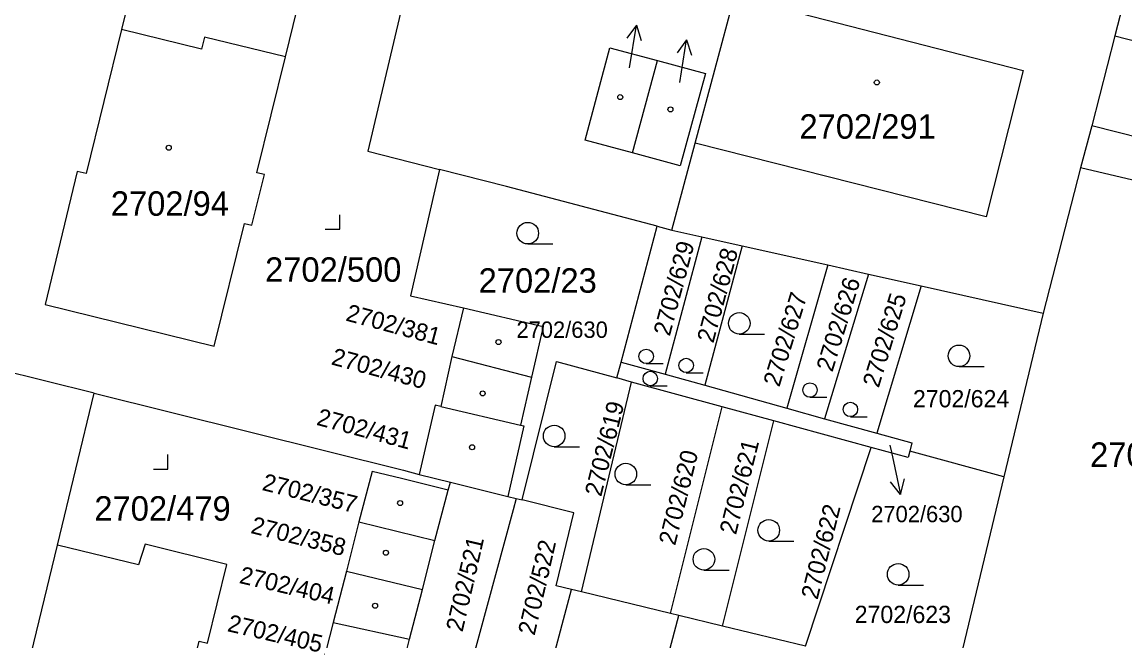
# Model space of a CAD drawing. Extents: x -496682 to -495907, y -1088575 to -1088018.
# Drawn here: x -496634.1 to -496557.4, y -1088480 to -1088436.9 of the extents above; entities that cross this region are included whole.
import ezdxf

# ---------------------------------------------------------------- set-up
doc = ezdxf.new("R2010")
doc.units = 0
for name, color, linetype in [('Hranice parcel', 7, 'Continuous'), ('Parcelní čísla', 7, 'Continuous'), ('Pop  PČ popisy', 7, 'Continuous'), ('Vnitřní kresba', 7, 'Continuous'), ('Značky budov', 7, 'Continuous'), ('Značky kultur', 7, 'Continuous')]:
    doc.layers.add(name, color=color, linetype=linetype)

msp = doc.modelspace()

# ---------------------------------------------------------------- linework, layer by layer
at = {"layer": 'Hranice parcel'}
for p, q in [((-496591.65, -1088446.03), (-496589.92, -1088439.6)), ((-496560.5, -1088447.06), (-496563.11, -1088457.17)), ((-496542.82, -1088451.3), (-496560.5, -1088447.06)), ((-496592.45, -1088460.57), (-496589.94, -1088451.12)), ((-496589.94, -1088451.12), (-496588.92, -1088451.39)), ((-496586.83, -1088451.86), (-496589.39, -1088461.42)), ((-496588.92, -1088451.39), (-496586.83, -1088451.86)), ((-496586.83, -1088451.86), (-496584.04, -1088452.48)), ((-496584.04, -1088452.48), (-496586.63, -1088462.19)), ((-496584.04, -1088452.48), (-496578.08, -1088453.82)), ((-496578.08, -1088453.82), (-496580.92, -1088463.77)), ((-496578.08, -1088453.82), (-496575.25, -1088454.45)), ((-496575.25, -1088454.45), (-496578.3, -1088464.51)), ((-496575.25, -1088454.45), (-496571.59, -1088455.27)), ((-496571.59, -1088455.27), (-496574.67, -1088465.51)), ((-496571.59, -1088455.27), (-496563.11, -1088457.17)), ((-496603.42, -1088456.81), (-496604.23, -1088460.18)), ((-496563.11, -1088457.17), (-496565.84, -1088468.56)), ((-496629.09, -1088462.74), (-496640.95, -1088459.81)), ((-496604.23, -1088460.18), (-496604.99, -1088463.66)), ((-496604.23, -1088460.18), (-496598.69, -1088461.62)), ((-496592.74, -1088461.68), (-496592.45, -1088460.57)), ((-496592.45, -1088460.57), (-496589.39, -1088461.42)), ((-496598.69, -1088461.62), (-496599.45, -1088464.96)), ((-496591.72, -1088461.96), (-496592.74, -1088461.68)), ((-496589.39, -1088461.42), (-496586.63, -1088462.19)), ((-496595.21, -1088476.56), (-496591.72, -1088461.96)), ((-496585.42, -1088463.68), (-496591.72, -1088461.96)), ((-496586.63, -1088462.19), (-496580.92, -1088463.77)), ((-496631.65, -1088473.31), (-496629.09, -1088462.74)), ((-496604.99, -1088463.66), (-496599.45, -1088464.96)), ((-496589.01, -1088478.06), (-496585.42, -1088463.68)), ((-496581.84, -1088464.65), (-496585.42, -1088463.68)), ((-496580.92, -1088463.77), (-496578.3, -1088464.51)), ((-496585.4, -1088478.93), (-496581.84, -1088464.65)), ((-496575.06, -1088466.51), (-496581.84, -1088464.65)), ((-496578.3, -1088464.51), (-496574.67, -1088465.51)), ((-496579.62, -1088480.33), (-496575.06, -1088466.51)), ((-496565.84, -1088468.56), (-496572.37, -1088466.76)), ((-496606.49, -1088468.38), (-496604.32, -1088468.92)), ((-496565.84, -1088468.56), (-496569.26, -1088482.83)), ((-496605.41, -1088472.99), (-496604.48, -1088469.49)), ((-496604.48, -1088469.49), (-496604.32, -1088468.92)), ((-496604.32, -1088468.92), (-496600.33, -1088469.91)), ((-496600.33, -1088469.91), (-496599.74, -1088470.06)), ((-496599.74, -1088470.06), (-496599.34, -1088470.16)), ((-496610.7, -1088471.68), (-496611.55, -1088475.11)), ((-496610.7, -1088471.68), (-496605.41, -1088472.99)), ((-496606.26, -1088476.38), (-496605.41, -1088472.99)), ((-496611.55, -1088475.11), (-496612.47, -1088478.69)), ((-496611.55, -1088475.11), (-496606.26, -1088476.38)), ((-496607.16, -1088479.85), (-496606.26, -1088476.38)), ((-496598.81, -1088487.34), (-496595.91, -1088476.39)), ((-496595.21, -1088476.56), (-496595.91, -1088476.39)), ((-496589.01, -1088478.06), (-496595.21, -1088476.56)), ((-496612.47, -1088478.69), (-496613.22, -1088481.59)), ((-496612.47, -1088478.69), (-496607.16, -1088479.85)), ((-496591.38, -1088489.16), (-496588.43, -1088478.2)), ((-496588.43, -1088478.2), (-496589.01, -1088478.06)), ((-496585.4, -1088478.93), (-496588.43, -1088478.2)), ((-496579.62, -1088480.33), (-496585.4, -1088478.93)), ((-496607.91, -1088482.74), (-496607.16, -1088479.85))]:
    msp.add_line(p, q, dxfattribs=at)
for points in [[(-496604.37, -1088422.13), (-496608.3, -1088421.17), (-496608.71, -1088419.97), (-496609.79, -1088419.25), (-496610.72, -1088418.98), (-496611.54, -1088418.92), (-496612.71, -1088420.08), (-496614.73, -1088419.57), (-496615.21, -1088421.34), (-496624.21, -1088419.11), (-496624.28, -1088419.41), (-496625.26, -1088419.65), (-496626.06, -1088420.8), (-496626.41, -1088422.72), (-496626.22, -1088423.74), (-496625.45, -1088424.47), (-496626.8, -1088429.92), (-496625.42, -1088430.27), (-496627.19, -1088437.45)], [(-496588.92, -1088451.39), (-496587.3, -1088445.36), (-496584.56, -1088435.13), (-496580.96, -1088421.7)], [(-496555.62, -1088428.18), (-496558.12, -1088437.89), (-496559.72, -1088444.15), (-496560.5, -1088447.06)], [(-496615.79, -1088439.35), (-496613.9, -1088431.66), (-496607.1, -1088433.31)], [(-496607.1, -1088433.31), (-496610.07, -1088445.9), (-496605.08, -1088447.17)], [(-496627.19, -1088437.45), (-496629.65, -1088447.47), (-496630.27, -1088447.33), (-496632.51, -1088456.57), (-496620.75, -1088459.46), (-496618.65, -1088450.94), (-496618.13, -1088451.06), (-496617.25, -1088447.52), (-496617.78, -1088447.42), (-496615.79, -1088439.35)], [(-496615.79, -1088439.35), (-496621.42, -1088437.97), (-496621.63, -1088438.82), (-496627.19, -1088437.45)], [(-496591.65, -1088446.03), (-496594.96, -1088445.15), (-496593.24, -1088438.71), (-496589.92, -1088439.6)], [(-496589.92, -1088439.6), (-496586.59, -1088440.5), (-496588.34, -1088446.92), (-496591.65, -1088446.03)], [(-496605.08, -1088447.17), (-496607.1, -1088455.97), (-496603.42, -1088456.81)], [(-496589.94, -1088451.12), (-496600.43, -1088448.36), (-496605.08, -1088447.17)], [(-496603.42, -1088456.81), (-496597.88, -1088458.09), (-496598.69, -1088461.62)], [(-496599.34, -1088470.16), (-496596.95, -1088460.53), (-496592.74, -1088461.68)], [(-496629.09, -1088462.74), (-496607.59, -1088468.1), (-496606.49, -1088468.38)], [(-496604.99, -1088463.66), (-496605.38, -1088463.57), (-496606.49, -1088468.38)], [(-496599.45, -1088464.96), (-496599.21, -1088465.01), (-496600.33, -1088469.91)], [(-496574.67, -1088465.51), (-496572.24, -1088466.19), (-496572.37, -1088466.76)], [(-496572.37, -1088466.76), (-496572.48, -1088467.21), (-496575.06, -1088466.51)], [(-496604.48, -1088469.49), (-496607.73, -1088468.68), (-496609.76, -1088468.18), (-496610.7, -1088471.68)], [(-496599.74, -1088470.06), (-496599.96, -1088470.85), (-496604.09, -1088486.04)], [(-496595.91, -1088476.39), (-496596.96, -1088476.14), (-496595.73, -1088471.05), (-496599.34, -1088470.16)], [(-496637.35, -1088497.34), (-496634.78, -1088486.77), (-496635.48, -1088486.6), (-496634.95, -1088484.46), (-496634.38, -1088484.6), (-496631.65, -1088473.31)], [(-496625.56, -1088500.2), (-496624.06, -1088494.16), (-496625.17, -1088493.89), (-496624.28, -1088490.18), (-496622.15, -1088490.71), (-496621.22, -1088487), (-496623.35, -1088486.47), (-496621.79, -1088479.99), (-496621.21, -1088480.13), (-496619.86, -1088474.64), (-496625.54, -1088473.24), (-496626, -1088474.67), (-496631.65, -1088473.31)]]:
    msp.add_lwpolyline(points, dxfattribs=at)
at = {"layer": 'Pop  PČ popisy'}
for p, q in [((-496591.391, -1088437.136), (-496592.042, -1088438.047)), ((-496591.86, -1088440.1), (-496591.391, -1088437.136)), ((-496591.391, -1088437.136), (-496591.053, -1088438.203)), ((-496587.901, -1088438.166), (-496588.552, -1088439.077)), ((-496588.37, -1088441.13), (-496587.901, -1088438.166)), ((-496587.901, -1088438.166), (-496587.563, -1088439.233)), ((-496573.77, -1088466.34), (-496573.65, -1088466.84)), ((-496573.65, -1088466.84), (-496573.026, -1088469.775)), ((-496573.026, -1088469.775), (-496572.744, -1088468.692)), ((-496573.026, -1088469.775), (-496573.724, -1088468.9))]:
    msp.add_line(p, q, dxfattribs=at)
at = {"layer": 'Vnitřní kresba'}
for p, q in [((-496584.56, -1088435.13), (-496564.48, -1088440.29)), ((-496558.12, -1088437.89), (-496554.65, -1088438.77)), ((-496564.48, -1088440.29), (-496567.06, -1088450.48)), ((-496556.25, -1088445.03), (-496559.72, -1088444.15)), ((-496567.06, -1088450.48), (-496587.3, -1088445.36))]:
    msp.add_line(p, q, dxfattribs=at)
at = {"layer": 'Značky budov'}
for centre in [(-496574.667, -1088441.129), (-496592.507, -1088442.149), (-496589.017, -1088442.999), (-496623.907, -1088445.669), (-496600.977, -1088459.179), (-496602.077, -1088462.749), (-496602.817, -1088466.499), (-496607.817, -1088470.379), (-496608.807, -1088473.829), (-496609.557, -1088477.519)]:
    msp.add_circle(centre, 0.175, dxfattribs=at)
at = {"layer": 'Značky kultur'}
for p, q in [((-496612.02, -1088451.34), (-496612.02, -1088450.34)), ((-496613.021, -1088451.34), (-496612.02, -1088451.34)), ((-496598.943, -1088452.36), (-496597.193, -1088452.36)), ((-496584.233, -1088458.63), (-496582.483, -1088458.63)), ((-496590.705, -1088460.68), (-496589.533, -1088460.68)), ((-496568.953, -1088460.89), (-496567.203, -1088460.89)), ((-496587.925, -1088461.31), (-496586.753, -1088461.31)), ((-496590.425, -1088462.22), (-496589.253, -1088462.22)), ((-496579.315, -1088463.02), (-496578.143, -1088463.02)), ((-496576.505, -1088464.37), (-496575.333, -1088464.37)), ((-496597.103, -1088466.46), (-496595.353, -1088466.46)), ((-496623.96, -1088468.01), (-496623.96, -1088467.01)), ((-496624.961, -1088468.01), (-496623.96, -1088468.01)), ((-496592.123, -1088469.11), (-496590.373, -1088469.11)), ((-496582.183, -1088473.02), (-496580.433, -1088473.02)), ((-496586.693, -1088475.04), (-496584.943, -1088475.04)), ((-496573.183, -1088476.08), (-496571.433, -1088476.08))]:
    msp.add_line(p, q, dxfattribs=at)
for centre, radius in [((-496598.943, -1088451.61), 0.75), ((-496584.233, -1088457.88), 0.75), ((-496568.953, -1088460.14), 0.75), ((-496590.705, -1088460.177), 0.502), ((-496587.925, -1088460.807), 0.502), ((-496590.425, -1088461.717), 0.502), ((-496579.315, -1088462.517), 0.502), ((-496576.505, -1088463.867), 0.502), ((-496597.103, -1088465.71), 0.75), ((-496592.123, -1088468.36), 0.75), ((-496582.183, -1088472.27), 0.75), ((-496586.693, -1088474.29), 0.75), ((-496573.183, -1088475.33), 0.75)]:
    msp.add_circle(centre, radius, dxfattribs=at)

# ---------------------------------------------------------------- texts
at = {"layer": 'Parcelní čísla'}
for s, height, p in [('2702/291', 1.7, (-496580.05, -1088445.04)), ('2702/94', 1.7, (-496627.938, -1088450.4)), ('2702/500', 1.7, (-496617.21, -1088454.99)), ('2702/23', 1.7, (-496602.358, -1088455.75)), ('2702/630', 1.139, (-496599.728, -1088458.889)), ('2702/624', 1.2, (-496572.155, -1088463.72)), ('2702/97', 1.7, (-496559.838, -1088467.86)), ('2702/479', 1.7, (-496629.08, -1088471.6)), ('2702/630', 1.139, (-496575.058, -1088471.709)), ('2702/623', 1.2, (-496576.205, -1088478.72))]:
    msp.add_text(s, height=height, dxfattribs=at).set_placement(p)
for s, rotation, p in [('2702/629', 75, (-496589.068, -1088458.825)), ('2702/628', 75, (-496586.038, -1088459.305)), ('2702/626', 73, (-496577.758, -1088461.315)), ('2702/627', 73, (-496581.448, -1088462.355)), ('2702/625', 73, (-496574.538, -1088462.415)), ('2702/381', 345, (-496611.658, -1088457.677)), ('2702/430', 345, (-496612.668, -1088460.727)), ('2702/619', 76, (-496593.834, -1088469.978)), ('2702/431', 345, (-496613.688, -1088464.927)), ('2702/621', 76, (-496584.464, -1088472.628)), ('2702/620', 76, (-496588.694, -1088473.378)), ('2702/357', 346, (-496617.475, -1088469.463)), ('2702/622', 76, (-496578.794, -1088477.138)), ('2702/358', 346, (-496618.265, -1088472.453)), ('2702/521', 77, (-496603.479, -1088479.39)), ('2702/522', 77, (-496598.469, -1088479.63)), ('2702/404', 347, (-496619.06, -1088475.93)), ('2702/405', 347, (-496619.89, -1088479.28))]:
    msp.add_text(s, height=1.2, rotation=rotation, dxfattribs=at).set_placement(p)

doc.saveas('drawing.dxf')
